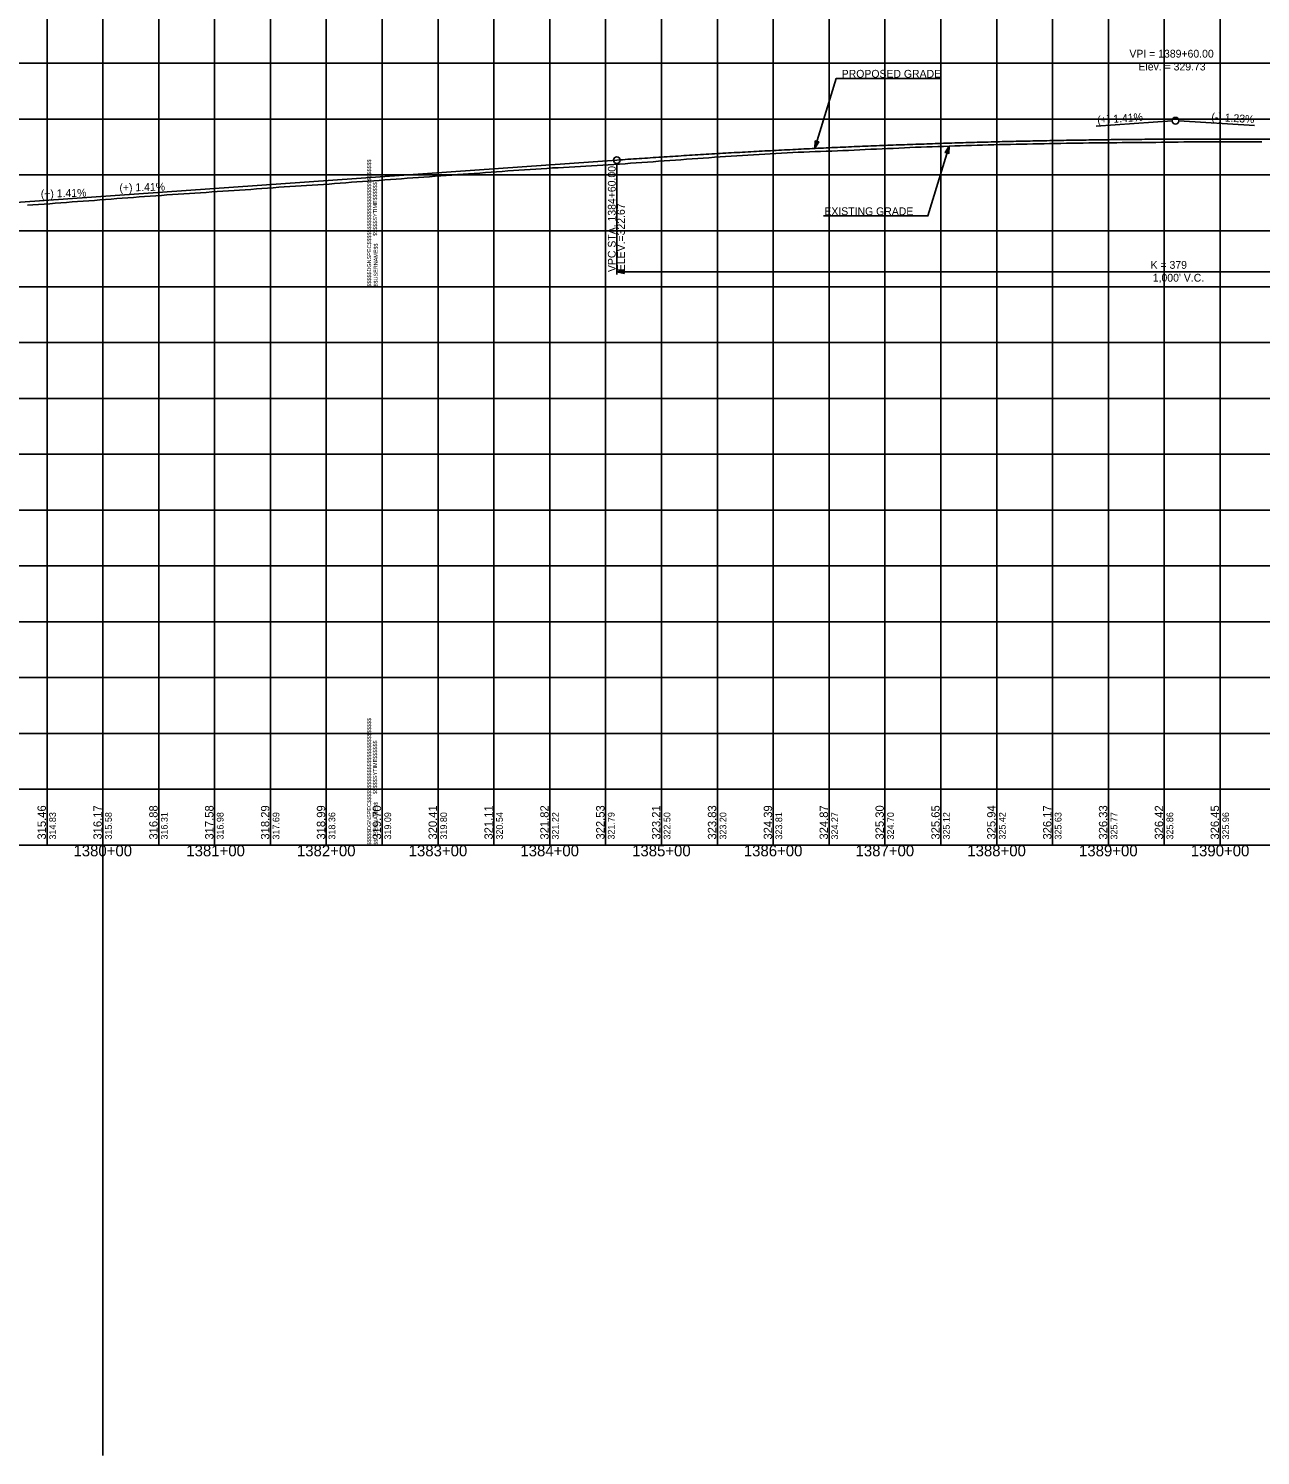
# Model space of a CAD drawing. Extents: x -90830 to 2015517, y -20856 to 836331.
# Drawn here: x 26857 to 27960, y -11344 to -10066 of the extents above; entities that cross this region are included whole.
import ezdxf

# ---------------------------------------------------------------- set-up
doc = ezdxf.new("R2010")
doc.units = 0
for name, color, linetype in [('Level 1', 7, 'Continuous'), ('RD_DDB_GradeTX', 7, 'Continuous'), ('RD_DDB_Profile_Elev', 7, 'Continuous'), ('RD_DDB_Profile_EX', 7, 'Continuous'), ('RD_DDB_Profile_Lbl', 7, 'Continuous'), ('RD_DDB_Profile_PR', 7, 'Continuous'), ('RD_DDB_StaTX', 7, 'Continuous'), ('RD_DDB_StripGrade', 7, 'Continuous'), ('RD_DDB_VCLbl', 7, 'Continuous'), ('RD_GPK_Profile_Cell', 7, 'Continuous'), ('RD_PD_Final_TX', 7, 'Continuous'), ('RD_TX_Drainage', 7, 'Continuous')]:
    doc.layers.add(name, color=color, linetype=linetype)

msp = doc.modelspace()

# ---------------------------------------------------------------- linework, layer by layer
at = {"layer": 'Level 1'}
for p, q in [((26923.5, -3180.8), (26923.5, -11343.5)), ((26873.5, -9797.1), (26873.5, -10297.1)), ((26923.5, -9797.1), (26923.5, -10297.1)), ((26973.5, -9797.1), (26973.5, -10297.1)), ((27023.5, -9797.1), (27023.5, -10297.1)), ((27073.5, -9797.1), (27073.5, -10297.1)), ((27123.5, -9797.1), (27123.5, -10297.1)), ((27173.5, -9797.1), (27173.5, -10297.1)), ((27173.5, -9797.1), (27173.5, -10297.1)), ((27173.5, -9797.1), (27173.5, -10297.1)), ((27223.5, -9797.1), (27223.5, -10297.1)), ((27273.5, -9797.1), (27273.5, -10297.1)), ((27323.5, -9797.1), (27323.5, -10297.1)), ((27373.5, -9797.1), (27373.5, -10297.1)), ((27423.5, -9797.1), (27423.5, -10297.1)), ((27473.5, -9797.1), (27473.5, -10297.1)), ((27523.5, -9797.1), (27523.5, -10297.1)), ((27573.5, -9797.1), (27573.5, -10297.1)), ((27623.5, -9797.1), (27623.5, -10297.1)), ((27673.5, -9797.1), (27673.5, -10297.1)), ((27723.5, -9797.1), (27723.5, -10297.1)), ((27773.5, -9797.1), (27773.5, -10297.1)), ((27823.5, -9797.1), (27823.5, -10297.1)), ((27873.5, -9797.1), (27873.5, -10297.1)), ((27923.5, -9797.1), (27923.5, -10297.1)), ((25573.5, -10097.1), (27173.5, -10097.1)), ((27173.5, -10097.1), (28773.5, -10097.1)), ((25573.5, -10147.1), (27173.5, -10147.1)), ((27173.5, -10147.1), (28773.5, -10147.1)), ((25573.5, -10197.1), (27173.5, -10197.1)), ((27173.5, -10197.1), (28773.5, -10197.1)), ((25573.5, -10247.1), (27173.5, -10247.1)), ((27173.5, -10247.1), (28773.5, -10247.1)), ((25573.5, -10297.1), (27173.5, -10297.1)), ((25573.5, -10297.1), (27173.5, -10297.1)), ((26873.5, -10297.1), (26873.5, -10797.1)), ((26923.5, -10297.1), (26923.5, -10797.1)), ((26973.5, -10297.1), (26973.5, -10797.1)), ((27023.5, -10297.1), (27023.5, -10797.1)), ((27073.5, -10297.1), (27073.5, -10797.1)), ((27123.5, -10297.1), (27123.5, -10797.1)), ((27173.5, -10297.1), (27173.5, -10797.1)), ((27173.5, -10297.1), (27173.5, -10797.1)), ((27173.5, -10297.1), (28773.5, -10297.1)), ((27173.5, -10297.1), (28773.5, -10297.1)), ((27173.5, -10297.1), (27173.5, -10797.1)), ((27223.5, -10297.1), (27223.5, -10797.1)), ((27273.5, -10297.1), (27273.5, -10797.1)), ((27323.5, -10297.1), (27323.5, -10797.1)), ((27373.5, -10297.1), (27373.5, -10797.1)), ((27423.5, -10297.1), (27423.5, -10797.1)), ((27473.5, -10297.1), (27473.5, -10797.1)), ((27523.5, -10297.1), (27523.5, -10797.1)), ((27573.5, -10297.1), (27573.5, -10797.1)), ((27623.5, -10297.1), (27623.5, -10797.1)), ((27673.5, -10297.1), (27673.5, -10797.1)), ((27723.5, -10297.1), (27723.5, -10797.1)), ((27773.5, -10297.1), (27773.5, -10797.1)), ((27823.5, -10297.1), (27823.5, -10797.1)), ((27873.5, -10297.1), (27873.5, -10797.1)), ((27923.5, -10297.1), (27923.5, -10797.1)), ((25573.5, -10347.1), (27173.5, -10347.1)), ((27173.5, -10347.1), (28773.5, -10347.1)), ((25573.5, -10397.1), (27173.5, -10397.1)), ((27173.5, -10397.1), (28773.5, -10397.1)), ((25573.5, -10447.1), (27173.5, -10447.1)), ((27173.5, -10447.1), (28773.5, -10447.1)), ((25573.5, -10497.1), (27173.5, -10497.1)), ((27173.5, -10497.1), (28773.5, -10497.1)), ((25573.5, -10547.1), (27173.5, -10547.1)), ((27173.5, -10547.1), (28773.5, -10547.1)), ((25573.5, -10597.1), (27173.5, -10597.1)), ((27173.5, -10597.1), (28773.5, -10597.1)), ((25573.5, -10647.1), (27173.5, -10647.1)), ((27173.5, -10647.1), (28773.5, -10647.1)), ((25573.5, -10697.1), (27173.5, -10697.1)), ((27173.5, -10697.1), (28773.5, -10697.1)), ((25573.5, -10747.1), (27173.5, -10747.1)), ((27173.5, -10747.1), (28773.5, -10747.1)), ((25573.5, -10797.1), (27173.5, -10797.1)), ((27173.5, -10797.1), (28773.5, -10797.1))]:
    msp.add_line(p, q, dxfattribs=at)
at = {"layer": 'RD_DDB_GradeTX'}
for p, q in [((27812.6, -10153.5), (27880.5, -10148.7)), ((27954.3, -10152.8), (27886.5, -10148.7))]:
    msp.add_line(p, q, dxfattribs=at)
msp.add_circle((27883.5, -10148.5), 3, dxfattribs=at)
at = {"layer": 'RD_DDB_Profile_EX'}
for points in [[(27545.9, -10176.8), (27550.9, -10176.6), (27555.9, -10176.4), (27560.9, -10176.2), (27565.9, -10176), (27570.9, -10175.9), (27575.9, -10175.7), (27580.9, -10175.5), (27585.9, -10175.3), (27590.9, -10175.1), (27595.9, -10174.8), (27600.9, -10174.6), (27605.9, -10174.3), (27610.9, -10174.1), (27615.9, -10173.9), (27620.9, -10173.7), (27625.9, -10173.5), (27630.9, -10173.3), (27635.9, -10173), (27640.9, -10172.7), (27645.9, -10172.5), (27650.9, -10172.3), (27655.9, -10172.1), (27660.9, -10172), (27665.9, -10171.8), (27670.9, -10171.6), (27675.9, -10171.5), (27680.9, -10171.3), (27685.9, -10171.1), (27690.9, -10171), (27695.9, -10170.8), (27700.9, -10170.6), (27705.9, -10170.5), (27710.9, -10170.4), (27715.9, -10170.2), (27720.9, -10170.1), (27725.9, -10169.9), (27730.9, -10169.8), (27735.9, -10169.7), (27740.9, -10169.6), (27745.9, -10169.5), (27750.9, -10169.4), (27755.9, -10169.3), (27760.9, -10169.2), (27765.9, -10169.1), (27770.9, -10169), (27775.9, -10168.9), (27780.9, -10168.8), (27785.9, -10168.7), (27790.9, -10168.6), (27795.9, -10168.5), (27800.9, -10168.5), (27805.9, -10168.4), (27810.9, -10168.3), (27815.9, -10168.3), (27820.9, -10168.3), (27825.9, -10168.2), (27830.9, -10168.2), (27835.9, -10168.1), (27840.9, -10168.1), (27845.9, -10168), (27850.9, -10168), (27855.9, -10168), (27860.9, -10167.9), (27865.9, -10167.9), (27870.9, -10167.8), (27875.9, -10167.8), (27880.9, -10167.7), (27885.9, -10167.6), (27890.9, -10167.5), (27895.9, -10167.5), (27900.9, -10167.5), (27905.9, -10167.4), (27910.9, -10167.4), (27915.9, -10167.4), (27920.9, -10167.3), (27925.9, -10167.3), (27930.9, -10167.3), (27935.9, -10167.3), (27940.9, -10167.3), (27945.9, -10167.3), (27950.9, -10167.3), (27955.9, -10167.4), (27960.9, -10167.5)], [(27045.9, -10210.7), (27050.9, -10210.4), (27055.9, -10210), (27060.9, -10209.6), (27065.9, -10209.3), (27070.9, -10208.9), (27075.9, -10208.5), (27080.9, -10208.1), (27085.9, -10207.7), (27090.9, -10207.4), (27095.9, -10207.1), (27100.9, -10206.8), (27105.9, -10206.5), (27110.9, -10206.2), (27115.9, -10205.8), (27120.9, -10205.5), (27125.9, -10205.2), (27130.9, -10204.8), (27135.9, -10204.4), (27140.9, -10204), (27145.9, -10203.6), (27150.9, -10203.3), (27155.9, -10202.9), (27160.9, -10202.5), (27165.9, -10202.2), (27170.9, -10201.9), (27175.9, -10201.5), (27180.9, -10201.2), (27185.9, -10200.8), (27190.9, -10200.5), (27195.9, -10200.1), (27200.9, -10199.8), (27205.9, -10199.4), (27210.9, -10199), (27215.9, -10198.7), (27220.9, -10198.3), (27225.9, -10197.9), (27230.9, -10197.6), (27235.9, -10197.2), (27240.9, -10196.8), (27245.9, -10196.4), (27250.9, -10196.1), (27255.9, -10195.7), (27260.9, -10195.4), (27265.9, -10195), (27270.9, -10194.6), (27275.9, -10194.3), (27280.9, -10193.9), (27285.9, -10193.5), (27290.9, -10193.2), (27295.9, -10192.8), (27300.9, -10192.4), (27305.9, -10192.1), (27310.9, -10191.8), (27315.9, -10191.5), (27320.9, -10191.2), (27325.9, -10190.8), (27330.9, -10190.6), (27335.9, -10190.3), (27340.9, -10190.1), (27345.9, -10189.8), (27350.9, -10189.5), (27355.9, -10189.2), (27360.9, -10189), (27365.9, -10188.7), (27370.9, -10188.3), (27375.9, -10188), (27380.9, -10187.7), (27385.9, -10187.3), (27390.9, -10187), (27395.9, -10186.6), (27400.9, -10186.3), (27405.9, -10185.9), (27410.9, -10185.5), (27415.9, -10185.2), (27420.9, -10184.8), (27425.9, -10184.5), (27430.9, -10184.1), (27435.9, -10183.7), (27440.9, -10183.4), (27445.9, -10183), (27450.9, -10182.6), (27455.9, -10182.3), (27460.9, -10181.9), (27465.9, -10181.6), (27470.9, -10181.3), (27475.9, -10180.9), (27480.9, -10180.6), (27485.9, -10180.3), (27490.9, -10180), (27495.9, -10179.7), (27500.9, -10179.4), (27505.9, -10179.1), (27510.9, -10178.8), (27515.9, -10178.5), (27520.9, -10178.2), (27525.9, -10177.9), (27530.9, -10177.6), (27535.9, -10177.4), (27540.9, -10177.1), (27545.9, -10176.8)], [(26855.9, -10224.2), (26860.9, -10223.9), (26865.9, -10223.5), (26870.9, -10223.1), (26875.9, -10222.8), (26880.9, -10222.4), (26885.9, -10222), (26890.9, -10221.6), (26895.9, -10221.2), (26900.9, -10220.9), (26905.9, -10220.5), (26910.9, -10220.1), (26915.9, -10219.8), (26920.9, -10219.4), (26925.9, -10219.1), (26930.9, -10218.7), (26935.9, -10218.3), (26940.9, -10217.9), (26945.9, -10217.6), (26950.9, -10217.2), (26955.9, -10216.8), (26960.9, -10216.5), (26965.9, -10216.1), (26970.9, -10215.7), (26975.9, -10215.4), (26980.9, -10215), (26985.9, -10214.7), (26990.9, -10214.3), (26995.9, -10214), (27000.9, -10213.6), (27005.9, -10213.3), (27010.9, -10213), (27015.9, -10212.7), (27020.9, -10212.3), (27025.9, -10212), (27030.9, -10211.7), (27035.9, -10211.4), (27040.9, -10211.1), (27045.9, -10210.7)]]:
    msp.add_lwpolyline(points, dxfattribs=at)
at = {"layer": 'RD_DDB_Profile_PR'}
msp.add_line((26228.5, -10265.4), (27383.5, -10183.8), dxfattribs=at)
msp.add_spline([(27383.5, -10183.8), (27403.5, -10182.4), (27423.5, -10181.1), (27443.5, -10179.8), (27463.5, -10178.6), (27483.5, -10177.4), (27503.5, -10176.3), (27523.5, -10175.2), (27543.5, -10174.2), (27563.5, -10173.2), (27583.5, -10172.3), (27603.5, -10171.4), (27623.5, -10170.6), (27643.5, -10169.9), (27663.5, -10169.2), (27683.5, -10168.5), (27703.5, -10167.9), (27723.5, -10167.4), (27743.5, -10166.9), (27763.5, -10166.5), (27783.5, -10166.1), (27803.5, -10165.8), (27823.5, -10165.5), (27843.5, -10165.3), (27863.5, -10165.1), (27883.5, -10165), (27903.5, -10164.9), (27923.5, -10164.9), (27943.5, -10164.9), (27963.5, -10165), (27983.5, -10165.2), (28003.5, -10165.4), (28023.5, -10165.6), (28043.5, -10165.9), (28063.5, -10166.3), (28083.5, -10166.7), (28103.5, -10167.1), (28123.5, -10167.6), (28143.5, -10168.2), (28163.5, -10168.8), (28183.5, -10169.5), (28203.5, -10170.2), (28223.5, -10171), (28243.5, -10171.8), (28263.5, -10172.7), (28283.5, -10173.7), (28303.5, -10174.6), (28323.5, -10175.7), (28343.5, -10176.8), (28363.5, -10177.9), (28383.5, -10179.1)], degree=3, dxfattribs=at)
at = {"layer": 'RD_DDB_VCLbl'}
for p, q in [((27383.5, -10286.3), (27383.5, -10186.8)), ((27383.5, -10283.8), (28383.5, -10283.8))]:
    msp.add_line(p, q, dxfattribs=at)
msp.add_circle((27383.5, -10183.8), 3, dxfattribs=at)
at = {"layer": 'RD_GPK_Profile_Cell'}
msp.add_line((4823.5, -10797.1), (75223.5, -10797.1), dxfattribs=at)
at = {"layer": 'RD_PD_Final_TX'}
for p, q in [((27560.8, -10173.2), (27561.1, -10166.5)), ((27562.7, -10167), (27560.8, -10173.2)), ((27560.8, -10173.2), (27564.2, -10167.5)), ((27561.1, -10166.5), (27564.2, -10167.5)), ((27680.9, -10171.3), (27677.5, -10177)), ((27680.6, -10178), (27677.5, -10177)), ((27679.1, -10177.5), (27680.9, -10171.3)), ((27680.9, -10171.3), (27680.6, -10178))]:
    msp.add_line(p, q, dxfattribs=at)
for points in [[(27673.2, -10110.8), (27579.8, -10110.8), (27560.8, -10173.2)], [(27562.6, -10167.1), (27560.8, -10172.8), (27562.6, -10167), (27560.9, -10172.6), (27562.5, -10167), (27560.9, -10172.4), (27562.4, -10167), (27560.9, -10172.1), (27562.4, -10167), (27560.9, -10171.8), (27562.3, -10166.9), (27560.9, -10171.4), (27562.2, -10167), (27561, -10171.1), (27562.1, -10166.9), (27561, -10170.8), (27562.1, -10166.9), (27561, -10170.5), (27562, -10166.9), (27561, -10170.2), (27561.9, -10166.9), (27561, -10169.9), (27561.8, -10166.8), (27561.1, -10169.4), (27561.8, -10166.8), (27561, -10169.1), (27561.7, -10166.8), (27561.1, -10168.7), (27561.6, -10166.8), (27561.1, -10168.3), (27561.5, -10166.7), (27561.1, -10168), (27561.5, -10166.7), (27561.1, -10167.7), (27561.4, -10166.6), (27561.2, -10167.3), (27561.3, -10166.7), (27561.2, -10166.9), (27561.2, -10166.7)], [(27560.9, -10172.8), (27562.7, -10167.1), (27561.1, -10172.6), (27562.8, -10167.1), (27561.1, -10172.4), (27562.8, -10167.1), (27561.3, -10172.3), (27562.9, -10167.1), (27561.4, -10172.1), (27562.9, -10167.2), (27561.5, -10171.9), (27563, -10167.2), (27561.6, -10171.7), (27563.1, -10167.2), (27561.8, -10171.4), (27563.2, -10167.2), (27561.9, -10171.2), (27563.2, -10167.2), (27562.1, -10170.9), (27563.3, -10167.2), (27562.2, -10170.7), (27563.3, -10167.3), (27562.4, -10170.4), (27563.4, -10167.3), (27562.6, -10170.1), (27563.4, -10167.3), (27562.7, -10169.9), (27563.5, -10167.3), (27562.9, -10169.6), (27563.6, -10167.3), (27563.1, -10169.3), (27563.6, -10167.4), (27563.2, -10169), (27563.7, -10167.4), (27563.4, -10168.8), (27563.8, -10167.5), (27563.6, -10168.4), (27563.9, -10167.4), (27563.7, -10168.2), (27564, -10167.5), (27563.8, -10168.1), (27564, -10167.6), (27564.1, -10167.5), (27564, -10167.5)], [(27568.5, -10233.7), (27661.9, -10233.7), (27680.9, -10171.3)], [(27680.8, -10171.7), (27679, -10177.4), (27680.7, -10171.9), (27679, -10177.4), (27680.6, -10172), (27678.9, -10177.4), (27680.5, -10172.2), (27678.9, -10177.4), (27680.3, -10172.4), (27678.8, -10177.3), (27680.2, -10172.6), (27678.7, -10177.3), (27680.1, -10172.8), (27678.7, -10177.3), (27679.9, -10173.1), (27678.6, -10177.3), (27679.8, -10173.3), (27678.5, -10177.3), (27679.7, -10173.6), (27678.5, -10177.3), (27679.5, -10173.8), (27678.4, -10177.2), (27679.3, -10174.1), (27678.4, -10177.2), (27679.1, -10174.4), (27678.3, -10177.2), (27679, -10174.6), (27678.2, -10177.2), (27678.8, -10174.9), (27678.2, -10177.2), (27678.7, -10175.2), (27678.1, -10177.1), (27678.5, -10175.5), (27678, -10177.1), (27678.3, -10175.7), (27678, -10177), (27678.2, -10176), (27677.9, -10177.1), (27678.1, -10176.3), (27677.8, -10177), (27677.9, -10176.4), (27677.7, -10176.9), (27677.6, -10177), (27677.7, -10176.9)], [(27679.1, -10177.4), (27680.9, -10171.7), (27679.2, -10177.5), (27680.9, -10171.9), (27679.2, -10177.5), (27680.9, -10172.1), (27679.3, -10177.5), (27680.9, -10172.4), (27679.4, -10177.5), (27680.8, -10172.7), (27679.5, -10177.5), (27680.8, -10173.1), (27679.5, -10177.5), (27680.8, -10173.4), (27679.6, -10177.6), (27680.8, -10173.7), (27679.7, -10177.6), (27680.7, -10174), (27679.7, -10177.6), (27680.7, -10174.3), (27679.8, -10177.6), (27680.7, -10174.6), (27679.9, -10177.7), (27680.7, -10175.1), (27680, -10177.7), (27680.7, -10175.4), (27680, -10177.7), (27680.7, -10175.8), (27680.1, -10177.7), (27680.6, -10176.2), (27680.2, -10177.8), (27680.6, -10176.5), (27680.3, -10177.8), (27680.6, -10176.8), (27680.3, -10177.8), (27680.6, -10177.2), (27680.4, -10177.8), (27680.6, -10177.6), (27680.5, -10177.8)]]:
    msp.add_lwpolyline(points, dxfattribs=at)
at = {"layer": 'RD_TX_Drainage'}
msp.add_lwpolyline([(27390.1, -10285.4), (27383.5, -10283.8), (27390.1, -10282.1)], close=True, dxfattribs=at)

# ---------------------------------------------------------------- texts
at = {"layer": 'Level 1'}
for s, p in [('$$$$$DGNSPEC$$$$$$$$$$$$$$$$$$$$$$$$$$$$', (27163.6, -10297.2)), ('$$$$$SYTIME$$$$$$', (27168.9, -10251.6)), ('$$USERNAME$$', (27169.5, -10297)), ('$$$$$DGNSPEC$$$$$$$$$$$$$$$$$$$$$$$$$$$$', (27163.6, -10797.2)), ('$$$$$SYTIME$$$$$$', (27168.9, -10751.6)), ('$$USERNAME$$', (27169.5, -10797))]:
    msp.add_text(s, height=3.544, rotation=90, dxfattribs=at).set_placement(p)
at = {"layer": 'RD_DDB_GradeTX'}
for s, rotation, p in [('(+) 1.41%', 4.04, (27813.8, -10151.4)), ('(-) 1.23%', 356.4902, (27915.5, -10148.4)), ('(+) 1.41%', 1.3637, (26938.4, -10212)), ('(+) 1.41%', 1.3637, (26868, -10217.4))]:
    msp.add_text(s, height=7, rotation=rotation, dxfattribs=at).set_placement(p)
at = {"layer": 'RD_DDB_Profile_Elev'}
for s, p in [('315.46', (26872.5, -10792.1)), ('316.17', (26922.5, -10792.1)), ('316.88', (26972.5, -10792.1)), ('317.58', (27022.5, -10792.1)), ('318.29', (27072.5, -10792.1)), ('318.99', (27122.5, -10792.1)), ('319.70', (27172.5, -10792.1)), ('320.41', (27222.5, -10792.1)), ('321.11', (27272.5, -10792.1)), ('321.82', (27322.5, -10792.1)), ('322.53', (27372.5, -10792.1)), ('323.21', (27422.5, -10792.1)), ('323.83', (27472.5, -10792.1)), ('324.39', (27522.5, -10792.1)), ('324.87', (27572.5, -10792.1)), ('325.30', (27622.5, -10792.1)), ('325.65', (27672.5, -10792.1)), ('325.94', (27722.5, -10792.1)), ('326.17', (27772.5, -10792.1)), ('326.33', (27822.5, -10792.1)), ('326.42', (27872.5, -10792.1)), ('326.45', (27922.5, -10792.1))]:
    msp.add_text(s, height=7.5, rotation=90, dxfattribs=at).set_placement(p)
at = {"layer": 'RD_DDB_Profile_Lbl'}
for s, p in [('VPI = 1389+60.00', (27842.3, -10092)), ('Elev. = 329.73', (27850.4, -10103.5))]:
    msp.add_text(s, height=7, dxfattribs=at).set_placement(p)
at = {"layer": 'RD_DDB_StaTX'}
for s, p in [('1380+00', (26897.2, -10807.1)), ('1381+00', (26998.2, -10807.1)), ('1382+00', (27097.2, -10807.1)), ('1383+00', (27197.2, -10807.1)), ('1384+00', (27297.2, -10807.1)), ('1385+00', (27397.2, -10807.1)), ('1386+00', (27497.2, -10807.1)), ('1387+00', (27597.2, -10807.1)), ('1388+00', (27697.2, -10807.1)), ('1389+00', (27797.2, -10807.1)), ('1390+00', (27897.2, -10807.1))]:
    msp.add_text(s, height=10, dxfattribs=at).set_placement(p)
at = {"layer": 'RD_DDB_StripGrade'}
for s, height, p in [('VPC STA. 1384+60.00 ', 7, (27382.5, -10284)), ('ELEV.=322.67', 7, (27390.7, -10283.2)), ('314.83', 6, (26881.5, -10792.1)), ('315.58', 6, (26931.5, -10792.1)), ('316.31', 6, (26981.5, -10792.1)), ('316.98', 6, (27031.5, -10792.1)), ('317.69', 6, (27081.5, -10792.1)), ('318.36', 6, (27131.5, -10792.1)), ('319.09', 6, (27181.5, -10792.1)), ('319.80', 6, (27231.5, -10792.1)), ('320.54', 6, (27281.5, -10792.1)), ('321.22', 6, (27331.5, -10792.1)), ('321.79', 6, (27381.5, -10792.1)), ('322.50', 6, (27431.5, -10792.1)), ('323.20', 6, (27481.5, -10792.1)), ('323.81', 6, (27531.5, -10792.1)), ('324.27', 6, (27581.5, -10792.1)), ('324.70', 6, (27631.5, -10792.1)), ('325.12', 6, (27681.5, -10792.1)), ('325.42', 6, (27731.5, -10792.1)), ('325.63', 6, (27781.5, -10792.1)), ('325.77', 6, (27831.5, -10792.1)), ('325.86', 6, (27881.5, -10792.1)), ('325.96', 6, (27931.5, -10792.1))]:
    msp.add_text(s, height=height, rotation=90, dxfattribs=at).set_placement(p)
at = {"layer": 'RD_DDB_VCLbl'}
for s, p in [('K = 379', (27861.3, -10281.1)), ("1,000' V.C.", (27863.2, -10292.6))]:
    msp.add_text(s, height=7, dxfattribs=at).set_placement(p)
at = {"layer": 'RD_PD_Final_TX'}
for s, p in [('PROPOSED GRADE', (27584.8, -10110)), ('EXISTING GRADE', (27569.3, -10233.1))]:
    msp.add_text(s, height=7, dxfattribs=at).set_placement(p)

doc.saveas('drawing.dxf')
